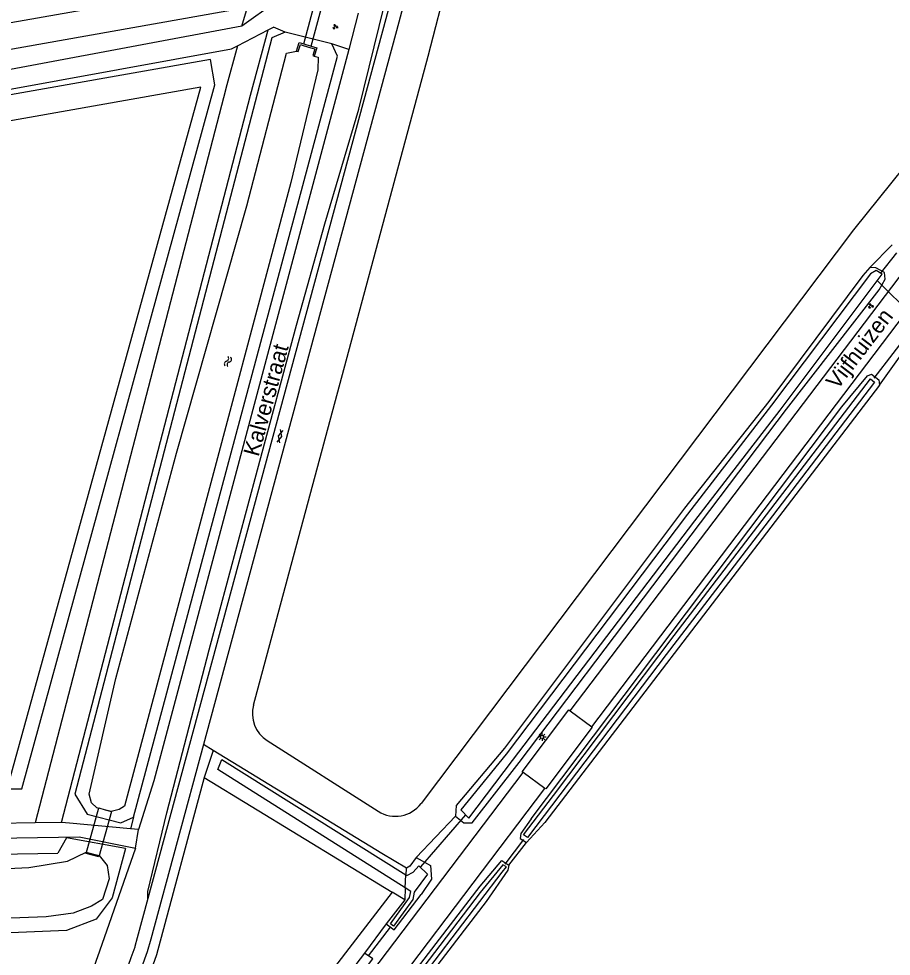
# Model space of a CAD drawing. Extents: x 133000 to 136000, y 400500 to 403500.
# Drawn here: x 134474.5 to 134610.2, y 401729.6 to 401875.4 of the extents above; entities that cross this region are included whole.
import ezdxf

# ---------------------------------------------------------------- set-up
doc = ezdxf.new("R2010")
doc.units = 0
for name, color, linetype in [('gg-anno-openbare ruimte label', 7, 'Continuous'), ('gg-knt-onverhard', 7, 'Continuous'), ('gg-knt-verharding', 7, 'Continuous'), ('gg-kntw-bovenkant insteek waterloop', 7, 'Continuous'), ('gg-kntw-waterlijn', 7, 'Continuous'), ('gg-kwrk-duiker nz buis', 7, 'Continuous'), ('gg-kwrk-duiker nz vlak', 7, 'Continuous'), ('gg-kwrk-uitstroombak niveau min 01', 7, 'Continuous'), ('gt-grn-groengrens', 7, 'Continuous'), ('gt-grn-vlakafsluiter', 7, 'Continuous'), ('gt-grn-weggrens', 7, 'Continuous'), ('gt-symb-gesloten verharding', 7, 'Continuous'), ('gt-symb-groenvak', 7, 'Continuous'), ('gt-symb-lichtmast', 7, 'Continuous'), ('gt-symb-watersymbool', 7, 'Continuous'), ('gx-grn-maaiveld', 7, 'Continuous')]:
    doc.layers.add(name, color=color, linetype=linetype)

# ---------------------------------------------------------------- blocks, each defined once
blk = doc.blocks.new('gt0-GRVAK')
at = {"layer": 'gt-symb-groenvak'}
for p, q in [((-0.11, 0.19), (-0.23, 0.24)), ((-0.18, 0.15), (0.09, 0.15)), ((-0.09, 0.21), (-0.16, 0.32)), ((-0.05, 0.21), (-0.05, 0.39)), ((0, 0.21), (0.06, 0.32)), ((0.01, 0.19), (0.13, 0.24)), ((0.26, -0.05), (0.2, 0.06)), ((0.3, -0.05), (0.3, 0.13)), ((0.35, -0.05), (0.41, 0.06)), ((-0.25, -0.23), (-0.36, -0.18)), ((-0.32, -0.26), (-0.05, -0.26)), ((-0.23, -0.21), (-0.29, -0.1)), ((-0.18, -0.2), (-0.18, -0.02)), ((-0.14, -0.21), (-0.07, -0.1)), ((-0.12, -0.23), (0, -0.18)), ((0.24, -0.07), (0.12, -0.02)), ((0.17, -0.11), (0.44, -0.11)), ((0.37, -0.07), (0.49, -0.02))]:
    blk.add_line(p, q, dxfattribs=at)
blk = doc.blocks.new('gt0-LMAST')
at = {"layer": 'gt-symb-lichtmast'}
for p, q in [((-0.18, 0.17), (-0.45, 0.44)), ((-0.01, 0.25), (-0.01, 0.62)), ((0.17, 0.17), (0.44, 0.44)), ((-0.26, 0), (-0.63, 0)), ((-0.18, -0.18), (-0.45, -0.45)), ((-0.01, -0.25), (-0.01, -0.63)), ((0.44, -0.45), (0.17, -0.18)), ((0.24, 0), (0.62, 0))]:
    blk.add_line(p, q, dxfattribs=at)
blk.add_circle((-0.01, 0), 0.25, dxfattribs=at)
blk = doc.blocks.new('gt0-GESVH1')
at = {"layer": 'gt-symb-gesloten verharding'}
for p, q in [((-0.99, -0.26), (0.01, 0.24)), ((0.01, -0.26), (-0.99, 0.24)), ((0.01, 0.24), (1.01, -0.26)), ((1.01, 0.24), (0.01, -0.26))]:
    blk.add_line(p, q, dxfattribs=at)
blk = doc.blocks.new('gt0-WA')
at = {"layer": 'gt-symb-watersymbool'}
for centre, start, end in [((-0.32, 0.02), 28.0725, 151.9275), ((0.43, 0.42), 208.0725, 331.9275), ((-0.32, -0.43), 28.0725, 151.9275), ((0.43, -0.03), 208.0725, 331.9275)]:
    blk.add_arc(centre, 0.425, start, end, dxfattribs=at)

msp = doc.modelspace()

# ---------------------------------------------------------------- linework, layer by layer
at = {"layer": 'gg-knt-onverhard'}
for p, q in [((134527.3, 401876.26), (134525.8, 401870.62)), ((134477.01, 401750.37), (134417.43, 401749.43)), ((134482.36, 401750.31), (134481.15, 401750.42)), ((134491.84, 401749.43), (134482.36, 401750.31)), ((134493.09, 401749.32), (134491.84, 401749.43))]:
    msp.add_line(p, q, dxfattribs=at)
for points in [[(134494.56, 401738.58), (134494.56, 401739.67), (134497.5, 401751.91), (134504.09, 401777.26), (134511.63, 401805.25), (134517.68, 401827.78), (134522.09, 401843.5), (134527.39, 401861.34), (134532.14, 401880.77), (134538.91, 401908.08), (134543.81, 401926.05), (134552.02, 401956.35), (134559.8, 401986.05), (134564.12, 402002.2), (134569.73, 402022.68), (134575.4, 402044.14), (134579.03, 402058.75), (134585.4, 402082.52), (134589.7, 402094.87), (134600.84, 402120.55), (134607.35, 402134.73), (134608.9, 402137.43)], [(134525.8, 401870.62), (134495.51, 401756.9), (134493.09, 401749.32)], [(134481.15, 401750.42), (134481.02, 401750.43), (134477.01, 401750.37)], [(134373.99, 401746.43), (134483.9, 401748.19), (134492.62, 401746.4)], [(134492.62, 401746.4), (134487.03, 401730.41), (134484.78, 401723.99)]]:
    msp.add_lwpolyline(points, dxfattribs=at)
at = {"layer": 'gg-knt-verharding'}
for p, q in [((134560.24, 401767.76), (134636.59, 401868.35)), ((134563.62, 401765.31), (134618.29, 401837.41)), ((134560.24, 401767.76), (134563.62, 401765.31)), ((134552.94, 401758.17), (134552.78, 401758.28)), ((134556.33, 401755.72), (134552.94, 401758.17)), ((134491.21, 401669.84), (134556.33, 401755.72)), ((134492.54, 401731.11), (134492.52, 401731.04))]:
    msp.add_line(p, q, dxfattribs=at)
for points in [[(134564.92, 402000), (134531.56, 401875.38), (134494.56, 401738.58)], [(134567.1, 402000), (134533.59, 401874.86), (134503.2, 401762.53)], [(134552.78, 401758.28), (134560.02, 401767.92), (134560.24, 401767.76)], [(134563.62, 401765.31), (134563.69, 401765.26), (134556.45, 401755.64), (134556.33, 401755.72)], [(134503.2, 401762.53), (134495.01, 401732.25), (134494.48, 401730.29)], [(134481.6, 401665.43), (134482.94, 401666.65), (134487.23, 401671.52), (134496.24, 401683.32), (134506.83, 401697.36), (134552.94, 401758.17)], [(134494.56, 401738.58), (134492.91, 401732.48), (134492.54, 401731.11)], [(134492.52, 401731.04), (134491.93, 401729.36), (134483.19, 401704.41), (134478.04, 401690.25), (134476.45, 401685.46)], [(134494.48, 401730.29), (134479.86, 401689.97), (134478.15, 401684.72)]]:
    msp.add_lwpolyline(points, dxfattribs=at)
at = {"layer": 'gg-kntw-bovenkant insteek waterloop'}
for p, q in [((134513.84, 401872.42), (134483.2, 401754.82)), ((134515.9, 401873.34), (134513.84, 401872.42)), ((134523.17, 401871.49), (134515.9, 401873.34)), ((134608.37, 401818.41), (134556.33, 401750.4)), ((134554.2, 401751.01), (134602.52, 401815.06)), ((134504.7, 401761.62), (134503.34, 401757.41)), ((134530.98, 401745.61), (134504.7, 401761.62)), ((134503.34, 401757.41), (134532.59, 401739.56)), ((134542.42, 401751.42), (134543.7, 401750.37)), ((134553.48, 401747.3), (134556.33, 401750.4)), ((134458.91, 401745.26), (134480.54, 401745.66)), ((134534.77, 401743.3), (134530.98, 401745.61)), ((134487.91, 401664.47), (134546.24, 401740.51)), ((134534.51, 401738.39), (134532.59, 401739.56)), ((134534.51, 401738.39), (134531.62, 401734.65))]:
    msp.add_line(p, q, dxfattribs=at)
for points in [[(134492.33, 401751.24), (134524.04, 401869.6), (134523.17, 401871.49)], [(134606.88, 401836.71), (134605.79, 401835.49), (134591.16, 401815.91), (134578.06, 401799.32), (134550.04, 401761.99), (134542.53, 401753.05), (134542.42, 401751.42)], [(134543.7, 401750.37), (134545.02, 401750.36), (134552.33, 401759.77), (134593.88, 401814.71), (134608.32, 401833.27), (134609.26, 401834.93), (134609.14, 401835.95), (134607.8, 401836.66), (134606.88, 401836.71)], [(134602.52, 401815.06), (134606.52, 401819.89), (134607.15, 401820.16), (134608.25, 401819.25), (134608.37, 401818.41)], [(134483.2, 401754.82), (134485.1, 401751.7), (134490.38, 401750.37), (134492.33, 401751.24)], [(134554.2, 401751.01), (134552.58, 401748.7), (134552.48, 401747.93), (134553.48, 401747.3)], [(134491.09, 401746.35), (134481.93, 401748.05), (134480.54, 401745.66)], [(134491.09, 401746.35), (134489.01, 401738.69), (134486.52, 401735.36), (134481.9, 401733.61), (134449.61, 401732.25)], [(134536.31, 401744.96), (134535.3, 401743.62), (134534.77, 401743.3)], [(134536.31, 401744.96), (134538.55, 401743.74), (134538.7, 401741.6), (134537.06, 401739.21)], [(134546.24, 401740.51), (134549.6, 401744.5), (134550.71, 401743.77)], [(134550.71, 401743.77), (134550.57, 401743.02), (134547.18, 401738.14)], [(134547.18, 401738.14), (134489.65, 401663.14), (134487.91, 401664.47)], [(134531.62, 401734.65), (134532.87, 401733.74), (134537.06, 401739.21)], [(134479.83, 401667.27), (134481.03, 401666), (134489.3, 401676.06), (134529.55, 401729.19), (134528.25, 401730.08)], [(134528.25, 401730.08), (134492.08, 401682.79), (134479.83, 401667.27)]]:
    msp.add_lwpolyline(points, dxfattribs=at)
at = {"layer": 'gg-kntw-waterlijn'}
for points in [[(134488.83, 401752.14), (134486.61, 401752.72), (134485.77, 401753.47), (134485.45, 401754.82), (134489.56, 401772.8), (134499.04, 401807.85), (134509.94, 401846.32), (134516.11, 401870.04), (134517.7, 401870.37)], [(134520.44, 401869.61), (134521.07, 401869.44), (134521.02, 401867.49), (134516.81, 401849.95), (134501.61, 401792.92), (134490.95, 401752.97), (134490.09, 401752.42), (134488.83, 401752.14)], [(134543.26, 401752.4), (134544.51, 401751.09), (134551.3, 401760.05), (134579.65, 401797.33), (134592.92, 401814.54), (134608.8, 401835.68), (134607.85, 401836.27), (134606.98, 401835.76), (134591.59, 401815.33), (134578.49, 401798.36), (134550.29, 401761.04), (134543.26, 401752.4)], [(134553, 401748.49), (134557.66, 401754.61), (134576.43, 401779.49), (134595.36, 401804.24), (134606.96, 401819.41), (134607.61, 401818.92), (134591.7, 401798.12), (134575.2, 401776.56), (134553.59, 401748.07), (134553, 401748.49)], [(134534.61, 401740.26), (134505.46, 401758.66), (134506.05, 401760.22), (134534.71, 401742.26)], [(134380.17, 401742.07), (134386.54, 401742.1), (134391.92, 401742.12), (134406.67, 401741.84), (134448.81, 401742.11), (134476.06, 401743.44), (134482.05, 401744.42), (134484.94, 401745.79), (134486.99, 401745.26)], [(134486.99, 401745.26), (134488.21, 401743.73), (134488.54, 401741.65), (134488.01, 401740.04), (134487.49, 401738.42), (134485.77, 401737.4), (134482.94, 401736.32), (134478.76, 401735.76), (134449.86, 401734.64), (134390.05, 401734.54), (134369.44, 401734.87)], [(134549.78, 401743.83), (134546.27, 401739.52), (134526.75, 401713.91), (134492.37, 401669.09), (134488.92, 401664.59), (134489.67, 401664.01), (134496.14, 401672.45), (134507.14, 401687.05), (134518.15, 401701.37), (134528.85, 401715.3), (134549.7, 401742.67), (134550.33, 401743.5), (134549.78, 401743.83)], [(134534.72, 401742.25), (134534.83, 401742.18), (134535.81, 401742.7), (134536.69, 401743.7), (134538.04, 401742.36), (134536.01, 401739.57), (134535.76, 401738.44), (134532.79, 401734.3), (134532.31, 401734.64), (134535.25, 401738.73), (134535.49, 401739.7), (134534.61, 401740.26)]]:
    msp.add_lwpolyline(points, dxfattribs=at)
at = {"layer": 'gg-kwrk-duiker nz buis'}
for p, q in [((134608.52, 401835.78), (134611.04, 401839)), ((134608.02, 401834.72), (134613.79, 401828.97)), ((134613.4, 401827.17), (134607.47, 401819.51)), ((134543.98, 401751.63), (134536.99, 401743.51)), ((134552.99, 401747.79), (134550.1, 401743.95)), ((134528.87, 401729.66), (134532.3, 401734.16))]:
    msp.add_line(p, q, dxfattribs=at)
at = {"layer": 'gg-kwrk-duiker nz vlak'}
for p, q in [((134518.81, 401871.51), (134520.69, 401878.5)), ((134519.96, 401871.16), (134521.86, 401878.23))]:
    msp.add_line(p, q, dxfattribs=at)
msp.add_lwpolyline([(134487.92, 401752.41), (134488.89, 401752.14), (134486.92, 401745.07), (134484.99, 401745.61), (134486.96, 401752.68), (134487.92, 401752.41)], dxfattribs=at)
at = {"layer": 'gg-kwrk-uitstroombak niveau min 01'}
for p, q in [((134518.74, 401871.26), (134519.89, 401870.91)), ((134518.81, 401871.51), (134519.96, 401871.16))]:
    msp.add_line(p, q, dxfattribs=at)
for points in [[(134517.7, 401870.37), (134518.11, 401871.72), (134518.81, 401871.51)], [(134517.7, 401870.37), (134517.95, 401870.3), (134518.28, 401871.4), (134518.74, 401871.26)], [(134519.89, 401870.91), (134520.51, 401870.73), (134520.2, 401869.69), (134520.44, 401869.61)], [(134519.96, 401871.16), (134520.83, 401870.9), (134520.44, 401869.61)]]:
    msp.add_lwpolyline(points, dxfattribs=at)
at = {"layer": 'gt-grn-groengrens'}
for p, q in [((134503.13, 401880.05), (134404.34, 401862.57)), ((134514.41, 401878.01), (134509.2, 401874.25)), ((134405.04, 401858.64), (134510.06, 401877.22)), ((134509.2, 401874.25), (134510.06, 401877.22)), ((134508.52, 401871.22), (134513.28, 401873.67)), ((134513.28, 401873.67), (134514.11, 401874.09)), ((134515.9, 401873.34), (134514.11, 401874.09)), ((134525.8, 401870.62), (134523.17, 401871.49)), ((134610.33, 401840.27), (134606.88, 401836.71)), ((134513.13, 401763.16), (134530.39, 401752.17)), ((134504.7, 401761.62), (134503.2, 401762.53)), ((134492.33, 401751.24), (134491.84, 401749.43)), ((134542.42, 401751.42), (134536.31, 401744.96)), ((134531.62, 401734.65), (134528.25, 401730.08))]:
    msp.add_line(p, q, dxfattribs=at)
for points in [[(134510.99, 401768.68), (134538.14, 401869.61), (134576.12, 402016.45), (134594.15, 402084.36), (134597.55, 402091.68)], [(134673.56, 401928.68), (134604.31, 401842.59), (134537.07, 401753.37)], [(134509.2, 401874.25), (134460.13, 401865.07), (134425.61, 401858.67), (134402.89, 401854.12)], [(134481.15, 401750.42), (134510.54, 401863.53), (134513.28, 401873.67)], [(134403.81, 401851.82), (134447.03, 401859.67), (134462.9, 401862.61), (134507.56, 401870.75), (134508.52, 401871.22)], [(134508.52, 401871.22), (134506.68, 401864.56), (134506.67, 401864.53), (134477.01, 401750.37)], [(134472.7, 401755.65), (134474.96, 401755.65), (134504.97, 401865.15), (134504.28, 401869.08), (134406.26, 401851.74), (134406.96, 401847.8)], [(134472.7, 401755.65), (134502.8, 401864.76), (134406.96, 401847.8)], [(134503.34, 401757.41), (134495.88, 401729.85), (134476.26, 401674.64)], [(134532.59, 401739.56), (134517.39, 401719.83), (134488.43, 401682.3), (134480.25, 401671.47), (134476.26, 401674.64)]]:
    msp.add_lwpolyline(points, dxfattribs=at)
for centre, start, end in [((134515.81, 401767.38), 164.9356, 237.5022), ((134533.08, 401756.38), 237.4977, 322.9897)]:
    msp.add_arc(centre, 5, start, end, dxfattribs=at)
at = {"layer": 'gt-grn-vlakafsluiter'}
for p, q in [((134608.37, 401818.41), (134613.79, 401826.05)), ((134550.71, 401743.77), (134553.48, 401747.3)), ((134534.72, 401742.25), (134534.77, 401743.3)), ((134534.61, 401740.26), (134534.71, 401742.26)), ((134534.61, 401740.26), (134534.51, 401738.39))]:
    msp.add_line(p, q, dxfattribs=at)
at = {"layer": 'gt-grn-weggrens'}
msp.add_line((134492.62, 401746.4), (134493.09, 401749.32), dxfattribs=at)
at = {"layer": 'gx-grn-maaiveld'}
for p, q in [((134534.72, 401742.25), (134534.71, 401742.26)), ((134534.61, 401740.26), (134534.61, 401740.26))]:
    msp.add_line(p, q, dxfattribs=at)

# ---------------------------------------------------------------- block references
at = {"layer": 'gt-symb-gesloten verharding', "rotation": 74.86552497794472}
msp.add_blockref('gt0-GESVH1', (134515.1, 401810.48), dxfattribs=at)
at = {"layer": 'gt-symb-groenvak'}
for p in [(134523.7, 401874.17), (134607.01, 401830.74)]:
    msp.add_blockref('gt0-GRVAK', p, dxfattribs=at)
at = {"layer": 'gt-symb-lichtmast'}
msp.add_blockref('gt0-LMAST', (134555.89, 401763.73), dxfattribs=at)
at = {"layer": 'gt-symb-watersymbool', "rotation": 73.26783977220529}
msp.add_blockref('gt0-WA', (134506.99, 401822.04), dxfattribs=at)

# ---------------------------------------------------------------- texts
at = {"layer": 'gg-anno-openbare ruimte label'}
for s, rotation, p in [('Vijfhuizen', 52.6, (134601.83, 401817.6)), ('Kalverstraat', 74.7, (134511.78, 401807.2))]:
    msp.add_text(s, height=2.5, rotation=rotation, dxfattribs=at).set_placement(p)

doc.saveas('drawing.dxf')
